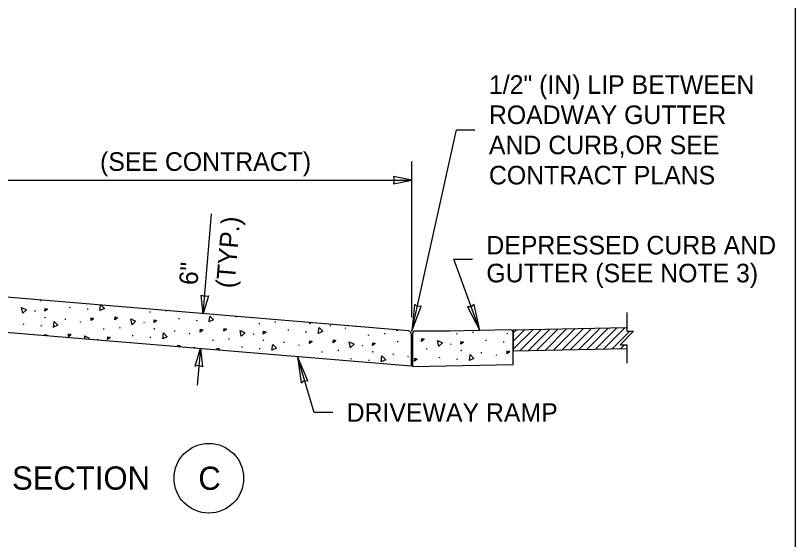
# Model space of a CAD drawing. Extents: x 99862 to 103151, y 100000 to 105076.
# Drawn here: x 102479 to 103151, y 100882 to 101333 of the extents above; entities that cross this region are included whole.
import ezdxf

# ---------------------------------------------------------------- set-up
doc = ezdxf.new("R2010")
doc.units = 0
for name, color, linetype in [('Level 1', 7, 'Continuous'), ('Level 13', 7, 'Continuous'), ('Level 15', 7, 'Continuous'), ('Level 20', 7, 'Continuous'), ('Level 48', 7, 'Continuous'), ('Level 6', 7, 'Continuous'), ('Level 7', 7, 'Continuous'), ('Level 9', 7, 'Continuous')]:
    doc.layers.add(name, color=color, linetype=linetype)

msp = doc.modelspace()

# ---------------------------------------------------------------- linework, layer by layer
at = {"layer": 'Level 1'}
msp.add_lwpolyline([(99862, 99999.5), (103151, 99999.5), (103151, 102075.5), (99862, 102075.5)], close=True, dxfattribs=at)
at = {"layer": 'Level 13'}
for p, q in [((102500.87, 101086.99), (102500.92, 101087.79)), ((102500.87, 101086.99), (102500.92, 101087.79)), ((102495.42, 101078.76), (102495.78, 101078.04)), ((102495.42, 101078.76), (102495.78, 101078.04)), ((102525.91, 101081.27), (102525.97, 101082.14)), ((102525.91, 101081.27), (102525.97, 101082.14)), ((102541.18, 101079.82), (102541.24, 101080.7)), ((102541.18, 101079.82), (102541.24, 101080.7)), ((102595, 101077.11), (102595.06, 101077.98)), ((102595, 101077.11), (102595.06, 101077.98)), ((102608.93, 101078.31), (102608.96, 101078.79)), ((102608.93, 101078.31), (102608.96, 101078.79)), ((102503.88, 101073.25), (102504.4, 101072.87)), ((102503.88, 101073.25), (102504.4, 101072.87)), ((102504.28, 101073.18), (102504.8, 101072.81)), ((102504.28, 101073.18), (102504.8, 101072.81)), ((102522.1, 101070.71), (102522.16, 101071.58)), ((102522.1, 101070.71), (102522.16, 101071.58)), ((102534.48, 101069.16), (102534.99, 101068.78)), ((102534.48, 101069.16), (102534.99, 101068.78)), ((102589.56, 101068.88), (102589.91, 101068.16)), ((102589.56, 101068.88), (102589.91, 101068.16)), ((102620.04, 101071.39), (102620.1, 101072.26)), ((102620.04, 101071.39), (102620.1, 101072.26)), ((102635.31, 101069.94), (102635.37, 101070.81)), ((102635.31, 101069.94), (102635.37, 101070.81)), ((102668.6, 101073.82), (102669.1, 101073.45)), ((102668.6, 101073.82), (102669.1, 101073.45)), ((102703.06, 101068.42), (102703.12, 101069.3)), ((102703.06, 101068.42), (102703.12, 101069.3)), ((102485.94, 101066.72), (102486, 101067.6)), ((102485.94, 101066.72), (102486, 101067.6)), ((102501.21, 101065.28), (102501.27, 101066.15)), ((102501.21, 101065.28), (102501.27, 101066.15)), ((102555.02, 101062.56), (102555.09, 101063.43)), ((102555.02, 101062.56), (102555.09, 101063.43)), ((102568.95, 101063.76), (102569.01, 101064.63)), ((102568.95, 101063.76), (102569.01, 101064.63)), ((102598.01, 101063.37), (102598.53, 101062.99)), ((102598.01, 101063.37), (102598.53, 101062.99)), ((102598.42, 101063.3), (102598.93, 101062.92)), ((102598.42, 101063.3), (102598.93, 101062.92)), ((102689.13, 101067.23), (102689.19, 101068.1)), ((102689.13, 101067.23), (102689.19, 101068.1)), ((102714.17, 101061.51), (102714.24, 101062.38)), ((102714.17, 101061.51), (102714.24, 101062.38)), ((102732.12, 101068.04), (102732.63, 101067.66)), ((102732.12, 101068.04), (102732.63, 101067.66)), ((102732.52, 101067.97), (102733.04, 101067.59)), ((102732.52, 101067.97), (102733.04, 101067.59)), ((102750.34, 101065.49), (102750.4, 101066.36)), ((102750.34, 101065.49), (102750.4, 101066.36)), ((102762.71, 101063.95), (102763.23, 101063.57)), ((102762.71, 101063.95), (102763.23, 101063.57)), ((102580.07, 101056.84), (102580.13, 101057.71)), ((102580.07, 101056.84), (102580.13, 101057.71)), ((102595.34, 101055.39), (102595.4, 101056.27)), ((102595.34, 101055.39), (102595.4, 101056.27)), ((102616.23, 101060.82), (102616.29, 101061.7)), ((102616.23, 101060.82), (102616.29, 101061.7)), ((102628.61, 101059.28), (102629.12, 101058.9)), ((102628.61, 101059.28), (102629.12, 101058.9)), ((102683.69, 101059), (102684.04, 101058.28)), ((102683.69, 101059), (102684.04, 101058.28)), ((102729.44, 101060.06), (102729.5, 101060.93)), ((102729.44, 101060.06), (102729.5, 101060.93)), ((102783.26, 101057.35), (102783.32, 101058.22)), ((102783.26, 101057.35), (102783.32, 101058.22)), ((102797.19, 101058.54), (102797.25, 101059.41)), ((102797.19, 101058.54), (102797.25, 101059.41)), ((102859.34, 101058.49), (102859.4, 101059.36)), ((102859.34, 101058.49), (102859.4, 101059.36)), ((102873.27, 101059.68), (102873.33, 101060.56)), ((102873.27, 101059.68), (102873.33, 101060.56)), ((102902.33, 101059.3), (102902.85, 101058.92)), ((102902.33, 101059.3), (102902.85, 101058.92)), ((102902.73, 101059.23), (102903.25, 101058.85)), ((102902.73, 101059.23), (102903.25, 101058.85)), ((102549.58, 101054.33), (102549.89, 101053.71)), ((102549.58, 101054.33), (102549.89, 101053.71)), ((102649.16, 101052.68), (102649.22, 101053.55)), ((102649.16, 101052.68), (102649.22, 101053.55)), ((102663.09, 101053.87), (102663.15, 101054.75)), ((102663.09, 101053.87), (102663.15, 101054.75)), ((102692.14, 101053.49), (102692.66, 101053.11)), ((102692.14, 101053.49), (102692.66, 101053.11)), ((102692.55, 101053.42), (102693.06, 101053.04)), ((102692.55, 101053.42), (102693.06, 101053.04)), ((102710.37, 101050.94), (102710.43, 101051.81)), ((102710.37, 101050.94), (102710.43, 101051.81)), ((102722.74, 101049.4), (102723.26, 101049.02)), ((102722.74, 101049.4), (102723.26, 101049.02)), ((102777.82, 101049.12), (102778.18, 101048.4)), ((102777.82, 101049.12), (102778.18, 101048.4)), ((102808.31, 101051.62), (102808.37, 101052.5)), ((102808.31, 101051.62), (102808.37, 101052.5)), ((102853.9, 101050.26), (102854.26, 101049.54)), ((102853.9, 101050.26), (102854.26, 101049.54)), ((102884.39, 101052.77), (102884.45, 101053.64)), ((102884.39, 101052.77), (102884.45, 101053.64)), ((102899.66, 101051.32), (102899.72, 101052.19)), ((102899.66, 101051.32), (102899.72, 101052.19)), ((102674.2, 101046.96), (102674.26, 101047.83)), ((102674.2, 101046.96), (102674.26, 101047.83)), ((102689.47, 101045.51), (102689.53, 101046.38)), ((102689.47, 101045.51), (102689.53, 101046.38)), ((102743.29, 101042.8), (102743.35, 101043.67)), ((102743.29, 101042.8), (102743.35, 101043.67)), ((102757.22, 101043.99), (102757.28, 101044.86)), ((102757.22, 101043.99), (102757.28, 101044.86)), ((102786.28, 101043.61), (102786.79, 101043.23)), ((102786.28, 101043.61), (102786.79, 101043.23)), ((102786.68, 101043.54), (102787.2, 101043.16)), ((102786.68, 101043.54), (102787.2, 101043.16)), ((102804.5, 101041.06), (102804.56, 101041.93)), ((102804.5, 101041.06), (102804.56, 101041.93)), ((102833.3, 101045.14), (102833.36, 101046.01)), ((102833.3, 101045.14), (102833.36, 101046.01)), ((102862.36, 101044.75), (102862.87, 101044.37)), ((102862.36, 101044.75), (102862.87, 101044.37)), ((102862.76, 101044.68), (102863.28, 101044.3)), ((102862.76, 101044.68), (102863.28, 101044.3)), ((102880.58, 101042.2), (102880.64, 101043.08)), ((102880.58, 101042.2), (102880.64, 101043.08)), ((102768.33, 101037.08), (102768.39, 101037.95)), ((102768.33, 101037.08), (102768.39, 101037.95)), ((102783.6, 101035.63), (102783.66, 101036.5)), ((102783.6, 101035.63), (102783.66, 101036.5)), ((102816.87, 101039.52), (102817.39, 101039.14)), ((102816.87, 101039.52), (102817.39, 101039.14)), ((102844.42, 101038.22), (102844.48, 101039.09)), ((102844.42, 101038.22), (102844.48, 101039.09)), ((102859.68, 101036.77), (102859.74, 101037.64)), ((102859.68, 101036.77), (102859.74, 101037.64)), ((102892.95, 101040.66), (102893.47, 101040.28)), ((102892.95, 101040.66), (102893.47, 101040.28))]:
    msp.add_line(p, q, dxfattribs=at)
for points in [[(102551.63, 101078.9), (102552.27, 101083.51)], [(102551.63, 101078.9), (102552.27, 101083.51)], [(102552.83, 101083.46), (102555.51, 101080.69), (102551.71, 101078.93)], [(102552.83, 101083.46), (102555.51, 101080.69), (102551.71, 101078.93)], [(102485.29, 101076.47), (102484.21, 101081.48), (102488.33, 101079.48), (102485.36, 101076.53)], [(102485.29, 101076.47), (102484.21, 101081.48), (102488.33, 101079.48), (102485.36, 101076.53)], [(102504.22, 101078.29), (102504.46, 101080.74), (102506.59, 101080.1), (102504.22, 101078.29)], [(102504.22, 101078.29), (102504.46, 101080.74), (102506.59, 101080.1), (102504.22, 101078.29)], [(102511.66, 101064.35), (102512.36, 101069.43), (102515.54, 101066.15), (102511.74, 101064.38)], [(102511.66, 101064.35), (102512.36, 101069.43), (102515.54, 101066.15), (102511.74, 101064.38)], [(102544.03, 101070.18), (102544.27, 101072.63), (102546.39, 101071.99), (102544.03, 101070.18)], [(102544.03, 101070.18), (102544.27, 101072.63), (102546.39, 101071.99), (102544.03, 101070.18)], [(102564.49, 101070.88), (102564.73, 101073.33), (102566.86, 101072.68), (102564.49, 101070.88)], [(102564.49, 101070.88), (102564.73, 101073.33), (102566.86, 101072.68), (102564.49, 101070.88)], [(102579.42, 101066.59), (102578.35, 101071.6), (102582.46, 101069.6), (102579.49, 101066.65)], [(102579.42, 101066.59), (102578.35, 101071.6), (102582.46, 101069.6), (102579.49, 101066.65)], [(102598.35, 101068.41), (102598.59, 101070.86), (102600.72, 101070.22), (102598.35, 101068.41)], [(102598.35, 101068.41), (102598.59, 101070.86), (102600.72, 101070.22), (102598.35, 101068.41)], [(102645.76, 101069.02), (102646.46, 101074.1), (102649.64, 101070.81), (102645.84, 101069.05)], [(102645.76, 101069.02), (102646.46, 101074.1), (102649.64, 101070.81), (102645.84, 101069.05)], [(102638.16, 101060.3), (102638.4, 101062.75), (102640.53, 101062.11), (102638.16, 101060.3)], [(102638.16, 101060.3), (102638.4, 101062.75), (102640.53, 101062.11), (102638.16, 101060.3)], [(102658.62, 101060.99), (102658.87, 101063.44), (102660.99, 101062.8), (102658.62, 101060.99)], [(102658.62, 101060.99), (102658.87, 101063.44), (102660.99, 101062.8), (102658.62, 101060.99)], [(102739.89, 101059.14), (102740.6, 101064.21), (102743.78, 101060.93), (102739.98, 101059.17)], [(102739.89, 101059.14), (102740.6, 101064.21), (102743.78, 101060.93), (102739.98, 101059.17)], [(102772.26, 101064.97), (102772.28, 101065.18)], [(102772.26, 101064.97), (102772.28, 101065.18)], [(102772.51, 101065.16), (102772.26, 101064.97)], [(102772.51, 101065.16), (102772.26, 101064.97)], [(102807.66, 101061.37), (102807.47, 101062.24)], [(102807.66, 101061.37), (102807.47, 101062.24)], [(102808.46, 101062.16), (102807.72, 101061.43)], [(102808.46, 101062.16), (102807.72, 101061.43)], [(102504.24, 101057.51), (102504.3, 101058.08), (102506.42, 101057.44), (102506.29, 101057.34)], [(102504.24, 101057.51), (102504.3, 101058.08), (102506.42, 101057.44), (102506.29, 101057.34)], [(102524.52, 101056.33), (102524.76, 101058.78), (102526.89, 101058.13), (102524.52, 101056.33)], [(102524.52, 101056.33), (102524.76, 101058.78), (102526.89, 101058.13), (102524.52, 101056.33)], [(102538.89, 101054.62), (102538.37, 101057.05), (102542.48, 101055.05), (102541.81, 101054.38)], [(102538.89, 101054.62), (102538.37, 101057.05), (102542.48, 101055.05), (102541.81, 101054.38)], [(102558.38, 101053.86), (102558.62, 101056.31), (102560.75, 101055.67), (102558.38, 101053.86)], [(102558.38, 101053.86), (102558.62, 101056.31), (102560.75, 101055.67), (102558.38, 101053.86)], [(102605.79, 101054.47), (102606.49, 101059.55), (102609.67, 101056.26), (102605.87, 101054.5)], [(102605.79, 101054.47), (102606.49, 101059.55), (102609.67, 101056.26), (102605.87, 101054.5)], [(102673.55, 101056.71), (102672.48, 101061.72), (102676.59, 101059.72), (102673.62, 101056.76)], [(102673.55, 101056.71), (102672.48, 101061.72), (102676.59, 101059.72), (102673.62, 101056.76)], [(102692.48, 101058.53), (102692.73, 101060.98), (102694.85, 101060.33), (102692.48, 101058.53)], [(102692.48, 101058.53), (102692.73, 101060.98), (102694.85, 101060.33), (102692.48, 101058.53)], [(102618.8, 101047.97), (102618.89, 101048.9), (102621.02, 101048.25), (102620.46, 101047.83)], [(102618.8, 101047.97), (102618.89, 101048.9), (102621.02, 101048.25), (102620.46, 101047.83)], [(102699.92, 101044.59), (102700.62, 101049.66), (102703.8, 101046.38), (102700, 101044.62)], [(102699.92, 101044.59), (102700.62, 101049.66), (102703.8, 101046.38), (102700, 101044.62)], [(102732.29, 101050.42), (102732.53, 101052.87), (102734.66, 101052.22), (102732.29, 101050.42)], [(102732.29, 101050.42), (102732.53, 101052.87), (102734.66, 101052.22), (102732.29, 101050.42)], [(102752.76, 101051.11), (102753, 101053.56), (102755.12, 101052.92), (102752.76, 101051.11)], [(102752.76, 101051.11), (102753, 101053.56), (102755.12, 101052.92), (102752.76, 101051.11)], [(102767.68, 101046.82), (102766.61, 101051.83), (102770.72, 101049.84), (102767.75, 101046.88)], [(102767.68, 101046.82), (102766.61, 101051.83), (102770.72, 101049.84), (102767.75, 101046.88)], [(102786.62, 101048.64), (102786.86, 101051.09), (102788.98, 101050.45), (102786.62, 101048.64)], [(102786.62, 101048.64), (102786.86, 101051.09), (102788.98, 101050.45), (102786.62, 101048.64)], [(102828.84, 101052.25), (102829.08, 101054.71), (102831.2, 101054.06), (102828.84, 101052.25)], [(102828.84, 101052.25), (102829.08, 101054.71), (102831.2, 101054.06), (102828.84, 101052.25)], [(102843.76, 101047.97), (102842.69, 101052.98), (102846.8, 101050.98), (102843.83, 101048.02)], [(102843.76, 101047.97), (102842.69, 101052.98), (102846.8, 101050.98), (102843.83, 101048.02)], [(102862.7, 101049.79), (102862.94, 101052.24), (102865.06, 101051.59), (102862.7, 101049.79)], [(102862.7, 101049.79), (102862.94, 101052.24), (102865.06, 101051.59), (102862.7, 101049.79)], [(102632.58, 101046.82), (102632.51, 101047.17), (102633.36, 101046.75)], [(102632.58, 101046.82), (102632.51, 101047.17), (102633.36, 101046.75)], [(102652.63, 101045.15), (102652.75, 101046.43), (102654.88, 101045.78), (102653.9, 101045.04)], [(102652.63, 101045.15), (102652.75, 101046.43), (102654.88, 101045.78), (102653.9, 101045.04)], [(102902.5, 101041.68), (102902.75, 101044.13), (102904.87, 101043.49), (102902.5, 101041.68)], [(102902.5, 101041.68), (102902.75, 101044.13), (102904.87, 101043.49), (102902.5, 101041.68)], [(102794.05, 101034.71), (102794.76, 101039.78), (102797.94, 101036.5), (102794.14, 101034.74)], [(102794.05, 101034.71), (102794.76, 101039.78), (102797.94, 101036.5), (102794.14, 101034.74)], [(102822.73, 101035.24), (102822.97, 101037.69), (102825.09, 101037.05), (102822.73, 101035.24)], [(102822.73, 101035.24), (102822.97, 101037.69), (102825.09, 101037.05), (102822.73, 101035.24)], [(102870.13, 101035.85), (102870.84, 101040.93), (102874.02, 101037.64), (102870.22, 101035.88)], [(102870.13, 101035.85), (102870.84, 101040.93), (102874.02, 101037.64), (102870.22, 101035.88)]]:
    msp.add_lwpolyline(points, dxfattribs=at)
at = {"layer": 'Level 15'}
for p, q in [((102820.4, 101061.17), (102858.89, 101234.47)), ((102858.89, 101234.47), (102874.89, 101234.47)), ((102820.4, 101073.17), (102820.4, 101207.17)), ((102820.4, 101073.17), (102820.4, 101207.17)), ((102460.4, 101191.17), (102820.4, 101191.17)), ((102460.4, 101191.17), (102820.4, 101191.17)), ((102640.76, 101076.14), (102647.93, 101162.21)), ((102640.76, 101076.14), (102647.93, 101162.21)), ((102856.71, 101123.14), (102872.71, 101123.14)), ((102879.12, 101061.69), (102856.71, 101123.14)), ((102856.71, 101123.14), (102872.71, 101123.14)), ((102879.12, 101061.69), (102856.71, 101123.14)), ((102907.9, 101062.27), (103005.73, 101064.22)), ((102907.9, 101062.27), (102907.9, 101044.27)), ((102638.27, 101046.34), (102635.62, 101014.45)), ((102638.27, 101046.34), (102635.62, 101014.45)), ((102907.9, 101044.27), (103005.73, 101046.22)), ((102736.32, 100991.05), (102721.83, 101039.38)), ((102736.32, 100991.05), (102721.83, 101039.38)), ((102752.32, 100991.05), (102736.32, 100991.05)), ((102752.32, 100991.05), (102736.32, 100991.05))]:
    msp.add_line(p, q, dxfattribs=at)
for points in [[(102820.4, 101191.17), (102804.67, 101194.25), (102805.4, 101191.17), (102804.67, 101188.08)], [(102820.4, 101191.17), (102804.67, 101194.25), (102805.4, 101191.17), (102804.67, 101188.08)], [(102640.76, 101076.14), (102638.99, 101092.06), (102642, 101091.08), (102645.14, 101091.55)], [(102640.76, 101076.14), (102638.99, 101092.06), (102642, 101091.08), (102645.14, 101091.55)], [(102820.4, 101061.17), (102828.55, 101082.7), (102825.4, 101082.36), (102822.74, 101084.07)], [(102879.13, 101061.69), (102874.16, 101084.17), (102871.72, 101082.16), (102868.55, 101082.14)], [(102638.27, 101046.34), (102640.04, 101030.41), (102637.03, 101031.39), (102633.9, 101030.92)], [(102638.27, 101046.34), (102640.04, 101030.41), (102637.03, 101031.39), (102633.9, 101030.92)], [(102721.83, 101039.38), (102725.24, 101016.61), (102727.82, 101018.45), (102730.98, 101018.25)], [(102721.83, 101039.38), (102725.24, 101016.61), (102727.82, 101018.45), (102730.98, 101018.25)]]:
    msp.add_lwpolyline(points, close=True, dxfattribs=at)
msp.add_lwpolyline([(103005.73, 101077.03), (103005.73, 101061.03), (103011.54, 101061.03), (102999.92, 101049.42), (103005.73, 101049.42), (103005.73, 101033.42)], dxfattribs=at)
msp.add_lwpolyline([(103005.73, 101077.03), (103005.73, 101061.03), (103011.54, 101061.03), (102999.92, 101049.42), (103005.73, 101049.42), (103005.73, 101033.42)], dxfattribs=at)
at = {"layer": 'Level 48'}
for p, q in [((102907.9, 101045.48), (102925.03, 101062.61)), ((102907.9, 101052.55), (102917.81, 101062.46)), ((102907.9, 101059.62), (102910.6, 101062.32)), ((102913.87, 101044.39), (102932.24, 101062.75)), ((102921.09, 101044.53), (102939.46, 101062.9)), ((102928.3, 101044.67), (102946.67, 101063.04)), ((102935.52, 101044.82), (102953.89, 101063.19)), ((102942.74, 101044.96), (102961.1, 101063.33)), ((102949.95, 101045.11), (102968.32, 101063.47)), ((102957.17, 101045.25), (102975.53, 101063.62)), ((102964.38, 101045.4), (102982.75, 101063.76)), ((102971.6, 101045.54), (102989.96, 101063.91)), ((102978.81, 101045.68), (102997.18, 101064.05)), ((102986.03, 101045.83), (103004.39, 101064.2)), ((102993.24, 101045.97), (103008.3, 101061.03)), ((103000.46, 101046.12), (103003.76, 101049.42))]:
    msp.add_line(p, q, dxfattribs=at)
at = {"layer": 'Level 6'}
for p, q in [((102907.9, 101062.27), (103005.73, 101064.22)), ((102907.9, 101044.27), (103005.73, 101046.22))]:
    msp.add_line(p, q, dxfattribs=at)
at = {"layer": 'Level 7'}
for p, q in [((102817.48, 101061.41), (102464.04, 101090.86)), ((102817.48, 101061.41), (102464.04, 101090.86)), ((102905.35, 101062.21), (102852.9, 101061.17)), ((102905.35, 101062.21), (102852.9, 101061.17)), ((102460.4, 101061.17), (102819.77, 101031.22)), ((102460.4, 101061.17), (102819.77, 101031.22)), ((102819.77, 101058.92), (102819.77, 101031.22)), ((102819.77, 101058.92), (102819.77, 101031.22)), ((102821.02, 101058.67), (102821.02, 101030.53)), ((102821.02, 101058.67), (102821.02, 101030.53)), ((102852.9, 101061.17), (102823.52, 101061.17)), ((102852.9, 101061.17), (102823.52, 101061.17)), ((102907.9, 101032.27), (102907.9, 101059.72)), ((102907.9, 101032.27), (102907.9, 101059.72)), ((102821.02, 101030.53), (102907.9, 101032.27)), ((102821.02, 101030.53), (102907.9, 101032.27))]:
    msp.add_line(p, q, dxfattribs=at)
for centre, start, end in [((102905.4, 101059.72), 0, 91.14576), ((102905.4, 101059.72), 0, 91.14576), ((102817.27, 101058.92), 0, 85.23636), ((102817.27, 101058.92), 0, 85.23636), ((102823.52, 101058.67), 90, 180), ((102823.52, 101058.67), 90, 180)]:
    msp.add_arc(centre, 2.5, start, end, dxfattribs=at)
at = {"layer": 'Level 9'}
msp.add_circle((102645.57, 100934.39), 30, dxfattribs=at)
msp.add_circle((102645.57, 100934.39), 30, dxfattribs=at)

# ---------------------------------------------------------------- texts
at = {"layer": 'Level 20'}
for s, height, p in [('1/2" (IN) LIP BETWEEN', 16, (102886.91, 101265.47)), ('ROADWAY GUTTER', 16, (102886.91, 101239.47)), ('AND CURB,OR SEE', 16, (102886.91, 101213.47)), ('(SEE CONTRACT)', 16, (102551.8, 101199.17)), ('CONTRACT PLANS', 16, (102886.91, 101187.47)), ('DEPRESSED CURB AND', 16, (102884.71, 101127.14)), ('GUTTER (SEE NOTE 3)', 16, (102884.71, 101103.14)), ('SECTION', 20, (102475.99, 100924.57)), ('C', 20, (102636.52, 100924.39)), ('C', 20, (102636.52, 100924.39))]:
    msp.add_text(s, height=height, dxfattribs=at).set_placement(p)
for s, rotation, p in [('(TYP.)', 85.23636, (102667.59, 101097.63)), ('6"', 85.23636, (102635.7, 101100.28)), ('DRIVEWAY RAMP ', 360, (102764.31, 100983.05))]:
    msp.add_text(s, height=16, rotation=rotation, dxfattribs=at).set_placement(p)

doc.saveas('drawing.dxf')
